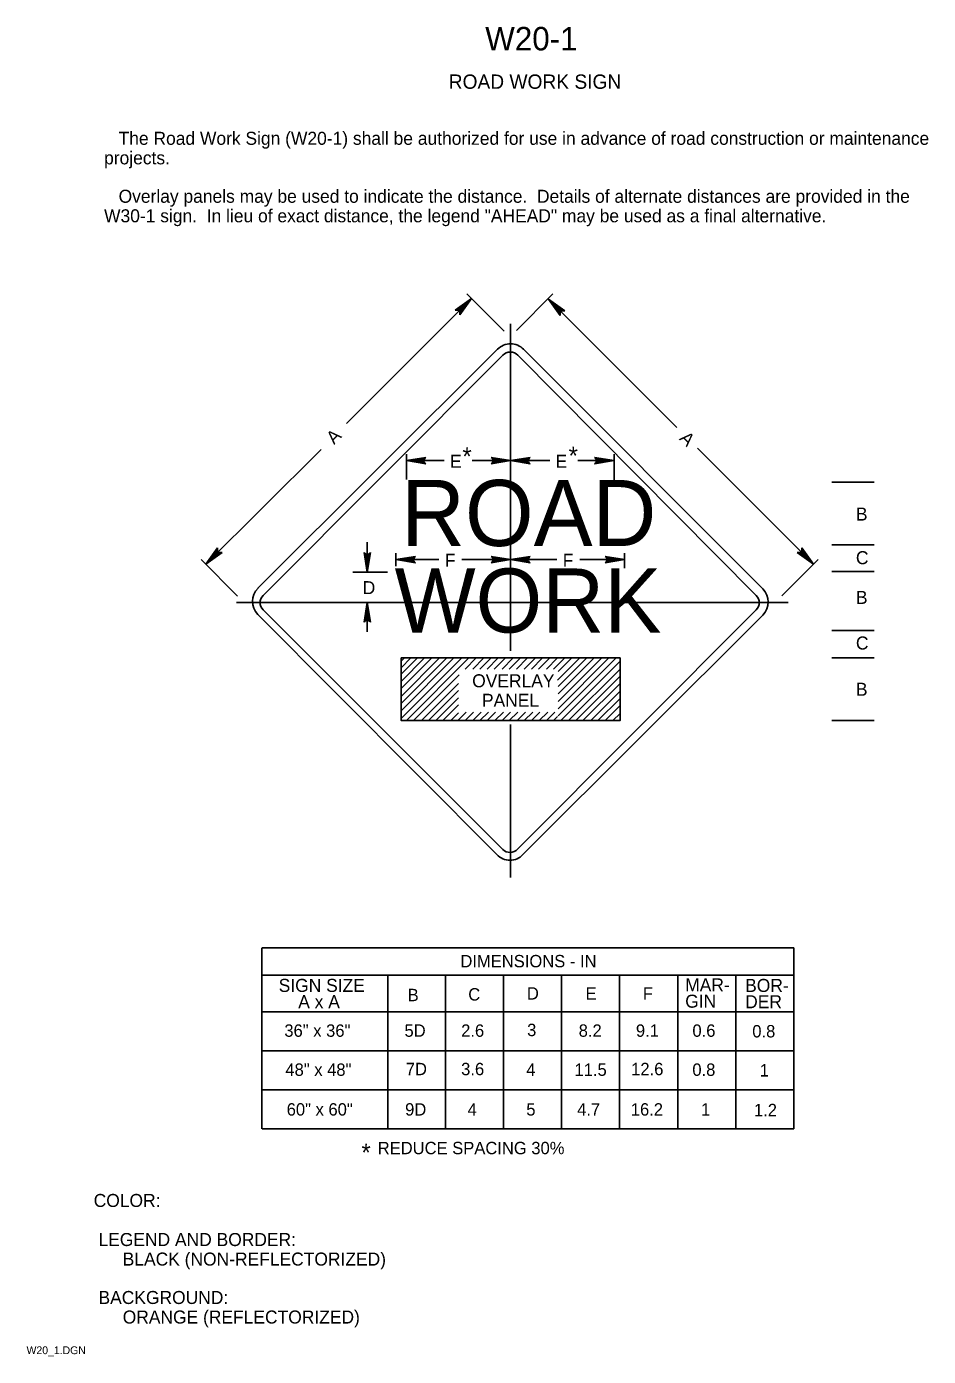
# Model space of a CAD drawing. Extents: x 0.013 to 0.186, y 0.004 to 0.259.
import ezdxf

# ---------------------------------------------------------------- set-up
doc = ezdxf.new("R2010")
doc.units = 0
for name, color, linetype in [('1', 7, 'Continuous'), ('2', 7, 'Continuous'), ('3', 7, 'Continuous')]:
    doc.layers.add(name, color=color, linetype=linetype)

# ---------------------------------------------------------------- blocks, each defined once
blk = doc.blocks.new('RARROW')
at = {"layer": '3'}
for p, q in [((-2.156, 0.28500000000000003), (-2.2665, 0.384625)), ((-2.2665, 0.384625), (0, 0)), ((0, 0), (-2.2665, -0.379125)), ((-2.156, 0.28500000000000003), (-2.075625, 0.12075)), ((0, 0), (-2.156, 0.28500000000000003)), ((-2.14975, -0.2705), (0, 0)), ((-2.075625, 0.12075), (0, 0)), ((0, 0), (-2.074, -0.108)), ((-2.2665, -0.379125), (-2.14975, -0.2705)), ((-2.074, -0.108), (-2.14975, -0.2705))]:
    blk.add_line(p, q, dxfattribs=at)

msp = doc.modelspace()

# ---------------------------------------------------------------- linework, layer by layer
at = {"layer": '3'}
for p, q in [((0.073875, 0.183), (0.097875, 0.20700000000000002)), ((0.09475, 0.20475000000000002), (0.097875, 0.20700000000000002)), ((0.097875, 0.20700000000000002), (0.095, 0.20475000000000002)), ((0.09525, 0.20475000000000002), (0.097875, 0.20700000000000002)), ((0.097875, 0.20700000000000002), (0.095625, 0.20450000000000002)), ((0.095625, 0.204125), (0.097875, 0.20700000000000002)), ((0.097875, 0.20700000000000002), (0.095625, 0.203875)), ((0.104125, 0.20075), (0.097, 0.207875)), ((0.1065, 0.200875), (0.1135, 0.207875)), ((0.13725, 0.18225), (0.112625, 0.206875)), ((0.114875, 0.20425000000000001), (0.112625, 0.206875)), ((0.112625, 0.206875), (0.114875, 0.20400000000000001)), ((0.114875, 0.20375000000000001), (0.112625, 0.206875)), ((0.112625, 0.206875), (0.115125, 0.204625)), ((0.1155, 0.204625), (0.112625, 0.206875)), ((0.112625, 0.206875), (0.11575, 0.204625)), ((0.095, 0.20475000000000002), (0.09475, 0.20475000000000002)), ((0.095, 0.20475000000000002), (0.09525, 0.20475000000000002)), ((0.095625, 0.20450000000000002), (0.095625, 0.204125)), ((0.114875, 0.20400000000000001), (0.114875, 0.20425000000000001)), ((0.115125, 0.204625), (0.1155, 0.204625)), ((0.11575, 0.204625), (0.1155, 0.204625)), ((0.095625, 0.203875), (0.095625, 0.204125)), ((0.105375, 0.202125), (0.105375, 0.139375)), ((0.114875, 0.20400000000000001), (0.114875, 0.20375000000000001)), ((0.10287500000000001, 0.19725), (0.056875, 0.151375)), ((0.15375, 0.15125), (0.107875, 0.19725)), ((0.10387500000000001, 0.196125), (0.057875, 0.15)), ((0.10387500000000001, 0.196125), (0.057875, 0.15)), ((0.1525, 0.15), (0.10675, 0.196125)), ((0.06899863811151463, 0.17800274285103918), (0.046875, 0.156)), ((0.085375, 0.17225000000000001), (0.085375, 0.177125)), ((0.105375, 0.173125), (0.105375, 0.177125)), ((0.12525, 0.172125), (0.12525, 0.177125)), ((0.14125000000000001, 0.17825), (0.1635, 0.156)), ((0.092625, 0.175875), (0.085375, 0.175875)), ((0.098, 0.175875), (0.105375, 0.175875)), ((0.112875, 0.175875), (0.105375, 0.175875)), ((0.11825000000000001, 0.175875), (0.12525, 0.175875)), ((0.167, 0.17175), (0.175125, 0.17175)), ((0.046875, 0.156), (0.049125, 0.15912500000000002)), ((0.049125, 0.15887500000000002), (0.046875, 0.156)), ((0.046875, 0.156), (0.049125, 0.1585)), ((0.049125, 0.15912500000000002), (0.049125, 0.15887500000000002)), ((0.049125, 0.1585), (0.049125, 0.15887500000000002)), ((0.077875, 0.1545), (0.077875, 0.16025)), ((0.16125, 0.15887500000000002), (0.16125, 0.15912500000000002)), ((0.16125, 0.15912500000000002), (0.1635, 0.156)), ((0.16125, 0.15887500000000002), (0.16125, 0.15862500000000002)), ((0.1635, 0.156), (0.16125, 0.15887500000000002)), ((0.16125, 0.15862500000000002), (0.1635, 0.156)), ((0.167, 0.15975), (0.175125, 0.15975)), ((0.053, 0.149875), (0.046, 0.15687500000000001)), ((0.0495, 0.15825), (0.046875, 0.156)), ((0.046875, 0.156), (0.04975, 0.15825)), ((0.05, 0.15825), (0.046875, 0.156)), ((0.04975, 0.15825), (0.0495, 0.15825)), ((0.04975, 0.15825), (0.05, 0.15825)), ((0.083375, 0.155625), (0.083375, 0.15812500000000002)), ((0.091625, 0.15687500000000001), (0.083375, 0.15687500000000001)), ((0.096, 0.15687500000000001), (0.105375, 0.15687500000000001)), ((0.105375, 0.154875), (0.105375, 0.15812500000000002)), ((0.11425, 0.15687500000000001), (0.105375, 0.15687500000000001)), ((0.11862500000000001, 0.15687500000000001), (0.12725, 0.15687500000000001)), ((0.12725, 0.15525), (0.12725, 0.15812500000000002)), ((0.15743749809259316, 0.14993749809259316), (0.164375, 0.15687500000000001)), ((0.1635, 0.156), (0.160375, 0.15825)), ((0.160375, 0.15825), (0.160625, 0.15825)), ((0.161, 0.15825), (0.160625, 0.15825)), ((0.160625, 0.15825), (0.1635, 0.156)), ((0.1635, 0.156), (0.161, 0.15825)), ((0.075125, 0.1545), (0.08175, 0.1545)), ((0.167, 0.154625), (0.175125, 0.154625)), ((0.05275, 0.148625), (0.15862500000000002, 0.148625)), ((0.077875, 0.148625), (0.077875, 0.14300000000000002)), ((0.056875, 0.146375), (0.10275000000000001, 0.10025)), ((0.057875, 0.14725), (0.10387500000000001, 0.10125)), ((0.106625, 0.10125), (0.1525, 0.14725)), ((0.10775, 0.10025), (0.15375, 0.14625)), ((0.167, 0.14325000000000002), (0.175125, 0.14325000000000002)), ((0.084375, 0.134875), (0.08750000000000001, 0.138)), ((0.084375, 0.1335), (0.088875, 0.138)), ((0.084375, 0.132125), (0.09025, 0.138)), ((0.084375, 0.130625), (0.09175, 0.138)), ((0.084375, 0.12925), (0.093125, 0.138)), ((0.084375, 0.12787500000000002), (0.0945, 0.138)), ((0.084375, 0.12637500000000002), (0.096, 0.138)), ((0.084375, 0.136125), (0.08625000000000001, 0.138)), ((0.084375, 0.137375), (0.085, 0.138)), ((0.085375, 0.126), (0.097375, 0.138)), ((0.096625, 0.135875), (0.09875, 0.138)), ((0.098125, 0.135875), (0.10025, 0.138)), ((0.0995, 0.135875), (0.10162500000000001, 0.138)), ((0.100875, 0.135875), (0.10300000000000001, 0.138)), ((0.10225000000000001, 0.135875), (0.104375, 0.138)), ((0.10375000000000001, 0.135875), (0.105875, 0.138)), ((0.105125, 0.135875), (0.10725, 0.138)), ((0.1065, 0.135875), (0.108625, 0.138)), ((0.108, 0.135875), (0.110125, 0.138)), ((0.109375, 0.135875), (0.1115, 0.138)), ((0.11075, 0.135875), (0.112875, 0.138)), ((0.11225, 0.135875), (0.114375, 0.138)), ((0.113625, 0.135875), (0.11575, 0.138)), ((0.114375, 0.13375), (0.11862500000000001, 0.138)), ((0.1145, 0.1325), (0.12, 0.138)), ((0.1145, 0.131125), (0.121375, 0.138)), ((0.1145, 0.129625), (0.122875, 0.138)), ((0.1145, 0.12825), (0.12425, 0.138)), ((0.1145, 0.12687500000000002), (0.12562500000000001, 0.138)), ((0.1145, 0.135375), (0.117125, 0.138)), ((0.167, 0.138), (0.175125, 0.138)), ((0.115, 0.126), (0.12637500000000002, 0.137375)), ((0.1165, 0.126), (0.12637500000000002, 0.135875)), ((0.08675000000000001, 0.126), (0.0955, 0.13475)), ((0.08825, 0.126), (0.095375, 0.133125)), ((0.11787500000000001, 0.126), (0.12637500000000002, 0.1345)), ((0.11925000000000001, 0.126), (0.12637500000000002, 0.133125)), ((0.089625, 0.126), (0.095375, 0.13175)), ((0.091, 0.126), (0.095375, 0.130375)), ((0.12075, 0.126), (0.12637500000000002, 0.131625)), ((0.122125, 0.126), (0.12637500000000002, 0.13025)), ((0.092375, 0.126), (0.095375, 0.129)), ((0.1235, 0.126), (0.12637500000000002, 0.128875)), ((0.093875, 0.126), (0.095375, 0.1275)), ((0.09525, 0.126), (0.096875, 0.12762500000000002)), ((0.096625, 0.126), (0.09825, 0.12762500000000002)), ((0.098125, 0.126), (0.09975, 0.12762500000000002)), ((0.0995, 0.126), (0.101125, 0.12762500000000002)), ((0.100875, 0.126), (0.10250000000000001, 0.12762500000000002)), ((0.10237500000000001, 0.126), (0.10400000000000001, 0.12762500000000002)), ((0.10375000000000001, 0.126), (0.105375, 0.12762500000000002)), ((0.105125, 0.126), (0.10675, 0.12762500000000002)), ((0.105375, 0.12525), (0.105375, 0.095875)), ((0.106625, 0.126), (0.10825, 0.12762500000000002)), ((0.108, 0.126), (0.109625, 0.12762500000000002)), ((0.109375, 0.126), (0.111, 0.12762500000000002)), ((0.110875, 0.126), (0.1125, 0.12762500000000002)), ((0.11225, 0.126), (0.113875, 0.12762500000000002)), ((0.113625, 0.126), (0.114375, 0.12675)), ((0.125, 0.126), (0.12637500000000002, 0.12737500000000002)), ((0.167, 0.126), (0.175125, 0.126)), ((0.057625, 0.082375), (0.057625, 0.047625)), ((0.05769820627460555, 0.08234882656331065), (0.15969820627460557, 0.08234882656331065)), ((0.15969820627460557, 0.07709882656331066), (0.05769820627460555, 0.07709882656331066)), ((0.08182320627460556, 0.07709882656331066), (0.08182320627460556, 0.047598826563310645)), ((0.05769820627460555, 0.07009882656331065), (0.15969820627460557, 0.07009882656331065)), ((0.05769820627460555, 0.06259882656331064), (0.15969820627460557, 0.06259882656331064)), ((0.05769820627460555, 0.055098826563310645), (0.15969820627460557, 0.055098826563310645)), ((0.05769820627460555, 0.047598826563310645), (0.15969820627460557, 0.047598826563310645))]:
    msp.add_line(p, q, dxfattribs=at)
msp.add_lwpolyline([(0.084375, 0.138), (0.12637500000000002, 0.138), (0.12637500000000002, 0.126), (0.084375, 0.126)], close=True, dxfattribs=at)
for points in [[(0.15969820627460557, 0.08234882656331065), (0.15969820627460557, 0.047598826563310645)], [(0.092875, 0.077125), (0.092875, 0.047625)], [(0.10400000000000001, 0.077125), (0.10400000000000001, 0.047625)], [(0.115125, 0.077125), (0.115125, 0.047625)], [(0.12625, 0.077125), (0.12625, 0.047625)], [(0.13744820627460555, 0.07709882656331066), (0.13744820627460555, 0.047598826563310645)], [(0.14857320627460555, 0.07709882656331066), (0.14857320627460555, 0.047598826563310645)]]:
    msp.add_lwpolyline(points, dxfattribs=at)
for centre, radius, start, end in [((0.10537499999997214, 0.19479022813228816), 0.0035072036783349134, 44.535291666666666, 135.46471111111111), ((0.10531249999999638, 0.19471063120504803), 0.0020166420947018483, 44.535291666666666, 135.46471111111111), ((0.05942928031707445, 0.14886019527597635), 0.003563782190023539, 134.98223055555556, 224.21459444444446), ((0.1512500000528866, 0.1487500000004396), 0.0035355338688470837, 315, 45), ((0.05925114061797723, 0.14862500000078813), 0.001945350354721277, 135.0237527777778, 224.97624444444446), ((0.15112499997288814, 0.14862499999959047), 0.0019445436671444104, 315, 45), ((0.10524999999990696, 0.10264162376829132), 0.0034597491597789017, 223.73079166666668, 316.2692055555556), ((0.10526849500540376, 0.10263108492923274), 0.0019619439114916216, 224.74373055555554, 317.28214444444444)]:
    msp.add_arc(centre, radius, start, end, dxfattribs=at)

# ---------------------------------------------------------------- block references
at = {"layer": '3', "xscale": 0.0016545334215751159, "yscale": 0.0016366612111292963}
for p, rotation in [((0.085375, 0.175875), 180), ((0.105375, 0.175875), 180), ((0.077875, 0.1545), -90.00000000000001), ((0.083375, 0.15687500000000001), 180), ((0.105375, 0.15687500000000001), 180), ((0.077875, 0.148625), 90)]:
    msp.add_blockref('RARROW', p, dxfattribs=dict(at, rotation=rotation))
for p in [(0.105375, 0.175875), (0.12525, 0.175875), (0.105375, 0.15687500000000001), (0.12725, 0.15687500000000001)]:
    msp.add_blockref('RARROW', p, dxfattribs=at)

# ---------------------------------------------------------------- texts
at = {"layer": '1'}
for s, height, p in [('W20-1', 0.0045000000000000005, (0.1005, 0.254625)), ('ROAD WORK SIGN', 0.00275025, (0.0935, 0.24725)), ('COLOR:', 0.0024997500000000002, (0.025375, 0.032625)), (' LEGEND AND BORDER:', 0.0024997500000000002, (0.025375, 0.025125)), ('      BLACK (NON-REFLECTORIZED)', 0.0024997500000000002, (0.025375, 0.021375)), (' BACKGROUND:', 0.0024997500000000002, (0.025375, 0.014)), ('      ORANGE (REFLECTORIZED)', 0.0024997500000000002, (0.025375, 0.01025)), ('W20_1.DGN', 0.0015, (0.0125, 0.004375))]:
    msp.add_text(s, height=height, dxfattribs=at).set_placement(p)
at = {"layer": '2'}
for s, p in [('   The Road Work Sign (W20-1) shall be authorized for use in advance of road construction or maintenance', (0.027375, 0.23650000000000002)), ('projects.', (0.027375, 0.23275)), ('   Overlay panels may be used to indicate the distance.  Details of alternate distances are provided in the ', (0.027375, 0.225375)), ('W30-1 sign.  In lieu of exact distance, the legend "AHEAD" may be used as a final alternative.', (0.027375, 0.22162500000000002))]:
    msp.add_text(s, height=0.0024997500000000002, dxfattribs=at).set_placement(p)
at = {"layer": '3'}
for rotation, p in [(45, (0.07150000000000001, 0.178875)), (315, (0.137625, 0.18))]:
    msp.add_text('A', height=0.0024997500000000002, rotation=rotation, dxfattribs=at).set_placement(p)
for s, height, p in [('E', 0.0024997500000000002, (0.09375, 0.17450000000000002)), ('*', 0.00342, (0.096125, 0.17500000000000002)), ('E', 0.0024997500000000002, (0.114, 0.17450000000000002)), ('*', 0.00342, (0.1165, 0.175125)), ('ROAD', 0.0126735, (0.084375, 0.1595)), ('B', 0.0024997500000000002, (0.171625, 0.164375)), ('C', 0.0024997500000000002, (0.171625, 0.156)), ('F', 0.0024997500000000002, (0.09275, 0.1555)), ('F', 0.0024997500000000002, (0.115375, 0.1555)), ('WORK', 0.012301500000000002, (0.083125, 0.142875)), ('D', 0.0024997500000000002, (0.077, 0.15025)), ('B', 0.0024997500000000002, (0.171625, 0.148375)), ('C', 0.0024997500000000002, (0.171625, 0.139625)), ('OVERLAY', 0.0024997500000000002, (0.098, 0.132375)), ('B', 0.0024997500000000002, (0.171625, 0.13075)), ('PANEL', 0.0024997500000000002, (0.099875, 0.128625)), ('DIMENSIONS - IN', 0.0023752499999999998, (0.09574049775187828, 0.078625)), ('SIGN SIZE', 0.0024997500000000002, (0.060875, 0.07390560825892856)), ('B', 0.0023752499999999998, (0.085625, 0.072125)), ('C', 0.0023752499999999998, (0.09725, 0.07225)), ('D', 0.0023752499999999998, (0.1085, 0.07243162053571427)), ('E', 0.0023752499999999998, (0.11975000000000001, 0.07239887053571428)), ('F', 0.0023752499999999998, (0.13075, 0.07242376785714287)), ('MAR-', 0.0024997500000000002, (0.138875, 0.07399845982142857)), ('BOR-', 0.0024997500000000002, (0.150375, 0.0738988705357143)), ('A x A', 0.0024997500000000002, (0.064625, 0.07078060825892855)), ('GIN', 0.0024997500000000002, (0.138875, 0.07087345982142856)), ('DER', 0.0024997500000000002, (0.150375, 0.0707738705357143)), ('36" x 36"', 0.0023752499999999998, (0.06195900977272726, 0.06529260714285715)), ('5D', 0.0023752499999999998, (0.08501200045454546, 0.06529260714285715)), ('2.6', 0.0023752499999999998, (0.09588304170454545, 0.06529260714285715)), ('3', 0.0023752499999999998, (0.10854259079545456, 0.06541760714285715)), ('8.2', 0.0023752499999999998, (0.11843450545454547, 0.06529260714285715)), ('9.1', 0.0023752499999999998, (0.12941399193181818, 0.06529260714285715)), ('0.6', 0.0023752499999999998, (0.14025804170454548, 0.06529260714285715)), ('0.8', 0.0023752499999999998, (0.15174508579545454, 0.06516760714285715)), ('48" x 48"', 0.0023752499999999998, (0.06215823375, 0.05779260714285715)), ('7D', 0.0023752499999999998, (0.08526200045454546, 0.05791760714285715)), ('3.6', 0.0023752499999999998, (0.09588304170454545, 0.05791760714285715)), ('4', 0.0023752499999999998, (0.1083715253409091, 0.05779260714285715)), ('11.5', 0.0023752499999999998, (0.11763592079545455, 0.05779260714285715)), ('12.6', 0.0023752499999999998, (0.12850804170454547, 0.05791760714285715)), ('0.8', 0.0023752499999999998, (0.14024508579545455, 0.05779260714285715)), ('1', 0.0023752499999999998, (0.1531639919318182, 0.05766760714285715)), ('60" x 60"', 0.0023752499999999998, (0.06240823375, 0.05016760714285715)), ('9D', 0.0023752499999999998, (0.08513700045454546, 0.05016760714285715)), ('4', 0.0023752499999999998, (0.0971215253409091, 0.05016760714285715)), ('5', 0.0023752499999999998, (0.10838592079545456, 0.05016760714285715)), ('4.7', 0.0023752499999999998, (0.11813844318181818, 0.05016760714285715)), ('16.2', 0.0023752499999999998, (0.12843450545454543, 0.05016760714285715)), ('1', 0.0023752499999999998, (0.1419139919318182, 0.05016760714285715)), ('1.2', 0.0023752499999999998, (0.15205950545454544, 0.05004260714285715)), ('*', 0.00342, (0.07675, 0.041375)), ('REDUCE SPACING 30%', 0.0023752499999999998, (0.079875, 0.04275))]:
    msp.add_text(s, height=height, dxfattribs=at).set_placement(p)

doc.saveas('drawing.dxf')
